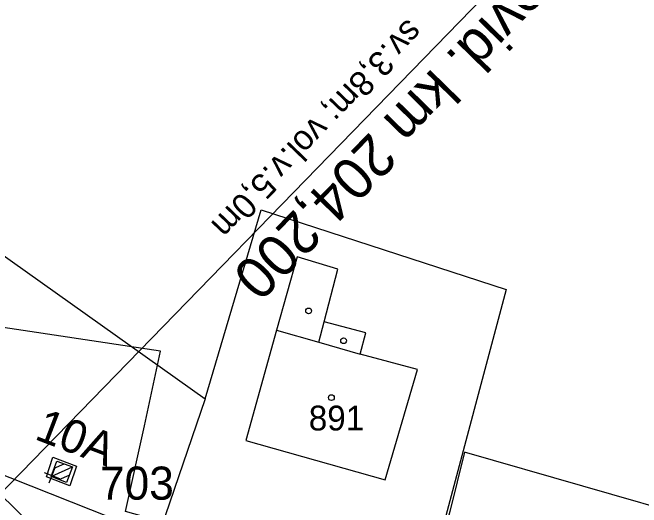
# Model space of a CAD drawing. Extents: x -800194 to -799078, y -1007177 to -1006597.
# Drawn here: x -799753.2 to -799715.24, y -1006975.25 to -1006945.35 of the extents above; entities that cross this region are included whole.
import ezdxf

# ---------------------------------------------------------------- set-up
doc = ezdxf.new("R2010")
doc.units = 0
for name, color, linetype in [('02_Osa_koleje', 7, 'Continuous'), ('Obvod stavby', 7, 'Continuous'), ('Vrstva 11', 7, 'Continuous'), ('Vrstva 12', 7, 'Continuous'), ('Vrstva 16', 7, 'Continuous'), ('Vrstva 17', 7, 'Continuous'), ('Vrstva 18', 7, 'Continuous'), ('Vrstva 55', 7, 'Continuous'), ('Vrstva 56', 7, 'Continuous'), ('Vrstva 57', 7, 'Continuous'), ('Vrstva 59', 7, 'Continuous'), ('Vrstva 7', 7, 'Continuous')]:
    doc.layers.add(name, color=color, linetype=linetype)

msp = doc.modelspace()

# ---------------------------------------------------------------- linework, layer by layer
at = {"layer": '02_Osa_koleje'}
msp.add_arc((-799651.022, -1006703.891), 292, 255.62486, 308.20516, dxfattribs=at)
at = {"layer": 'Obvod stavby'}
msp.add_lwpolyline([(-799664.426, -1006999.087), (-799684.601, -1006997.477), (-799704.619, -1006994.49), (-799724.386, -1006990.14), (-799749.554, -1006982.491), (-799772.102, -1006973.528), (-799780.707, -1006969.551), (-799777.674, -1006963.242), (-799769.263, -1006967.129), (-799747.228, -1006975.889), (-799722.648, -1006983.359), (-799703.35, -1006987.606), (-799683.806, -1006990.523), (-799664.228, -1006992.091)], dxfattribs=at)
at = {"layer": 'Vrstva 11'}
for p, q in [((-799750.69, -1006972.883), (-799750.087, -1006972.614)), ((-799750.88, -1006973.378), (-799749.592, -1006972.804)), ((-799750.389, -1006973.57), (-799749.778, -1006973.297))]:
    msp.add_line(p, q, dxfattribs=at)
msp.add_lwpolyline([(-799750.523, -1006972.447), (-799749.589, -1006972.805), (-799749.947, -1006973.739), (-799750.881, -1006973.381)], close=True, dxfattribs=at)
at = {"layer": 'Vrstva 12'}
msp.add_lwpolyline([(-799751.16, -1006973.407), (-799750.766, -1006972.211), (-799749.342, -1006972.749), (-799749.756, -1006973.956), (-799751.16, -1006973.407)], dxfattribs=at)
at = {"layer": 'Vrstva 16'}
msp.add_lwpolyline([(-799779.465, -1006951.506), (-799778.251, -1006952.583), (-799776.738, -1006953.884), (-799763.224, -1006965.504), (-799753.999, -1006974.421), (-799741.964, -1006986.204), (-799736.168, -1006991.012), (-799728.577, -1006997.215), (-799726.123, -1006999.163)], dxfattribs=at)
at = {"layer": 'Vrstva 17'}
for points in [[(-799726.806, -1006975.491), (-799728.174, -1006980.607), (-799746.39, -1006975.498), (-799745.242, -1006970.318), (-799744.263, -1006965.815), (-799756.721, -1006963.941)], [(-799695.807, -1006967.611), (-799698.37, -1006979.283), (-799711.621, -1006976.014), (-799725.913, -1006971.918), (-799726.806, -1006975.491)]]:
    msp.add_lwpolyline(points, dxfattribs=at)
at = {"layer": 'Vrstva 18'}
msp.add_line((-799754.68, -1006975.182), (-799715.262, -1006934.616), dxfattribs=at)
msp.add_lwpolyline([(-799776.738, -1006953.884), (-799763.224, -1006965.504), (-799753.999, -1006974.421), (-799741.964, -1006986.204), (-799736.168, -1006991.012)], dxfattribs=at)
at = {"layer": 'Vrstva 55'}
msp.add_line((-799785.23, -1006937.71), (-799741.57, -1006968.68), dxfattribs=at)
for points in [[(-799741.57, -1006968.68), (-799738.19, -1006957.26), (-799723.4, -1006962.09), (-799727.37, -1006976.97)], [(-799741.57, -1006968.68), (-799744.25, -1006976.52), (-799740.85, -1006977.38), (-799729.15, -1006978.91), (-799727.37, -1006976.97)]]:
    msp.add_lwpolyline(points, dxfattribs=at)
at = {"layer": 'Vrstva 56'}
for p, q in [((-799736.02, -1006960.1), (-799737.26, -1006964.54)), ((-799733.56, -1006960.86), (-799736.02, -1006960.1)), ((-799734.4, -1006964.04), (-799733.56, -1006960.86)), ((-799734.72, -1006965.27), (-799734.4, -1006964.04)), ((-799731.87, -1006964.71), (-799734.4, -1006964.04)), ((-799737.26, -1006964.54), (-799739.13, -1006971.21)), ((-799737.26, -1006964.54), (-799734.72, -1006965.27)), ((-799732.21, -1006965.99), (-799731.87, -1006964.71)), ((-799734.72, -1006965.27), (-799732.21, -1006965.99)), ((-799728.75, -1006966.91), (-799732.21, -1006965.99)), ((-799730.7, -1006973.58), (-799728.75, -1006966.91)), ((-799739.13, -1006971.21), (-799730.7, -1006973.58))]:
    msp.add_line(p, q, dxfattribs=at)
at = {"layer": 'Vrstva 59'}
for centre in [(-799735.327, -1006963.379), (-799733.217, -1006965.179), (-799733.957, -1006968.619)]:
    msp.add_circle(centre, 0.175, dxfattribs=at)
at = {"layer": 'Vrstva 7'}
for p, q in [((-799750.66, -1006972.855), (-799751.018, -1006973.789)), ((-799751.306, -1006973.143), (-799750.372, -1006973.501))]:
    msp.add_line(p, q, dxfattribs=at)

# ---------------------------------------------------------------- texts
at = {"layer": 'Obvod stavby'}
msp.add_text('703', height=2, rotation=360, dxfattribs=at).set_placement((-799747.93, -1006974.785))
at = {"layer": 'Vrstva 11'}
msp.add_text('10A', height=2, rotation=339.0461, dxfattribs=at).set_placement((-799751.944, -1006971.101))
at = {"layer": 'Vrstva 18'}
for s, height, rotation, p in [('evid. km 204,200', 2.5, 225.6357, (-799722.248, -1006942.945)), ('sv.3,8m; vol.v.5,0m', 1.5, 226.1315, (-799729.335, -1006945.66))]:
    msp.add_text(s, height=height, rotation=rotation, dxfattribs=at).set_placement(p)
at = {"layer": 'Vrstva 57'}
msp.add_text('891', height=1.5, dxfattribs=at).set_placement((-799735.32, -1006970.602))

doc.saveas('drawing.dxf')
